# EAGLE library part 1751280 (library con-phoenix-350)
MKDS 1/ 6-3,5 Printklemme Nennstrom: 10 A Bemessungsspannung: 160 V Raster: 3,5 mm Polzahl: 6 Montageart: Löten Anschlussart: Schraubanschluss Anschlussrichtung vom Leiter zur Platine: 0° Source: http://eshop.phoenixcontact.com .. 1751280.pdf
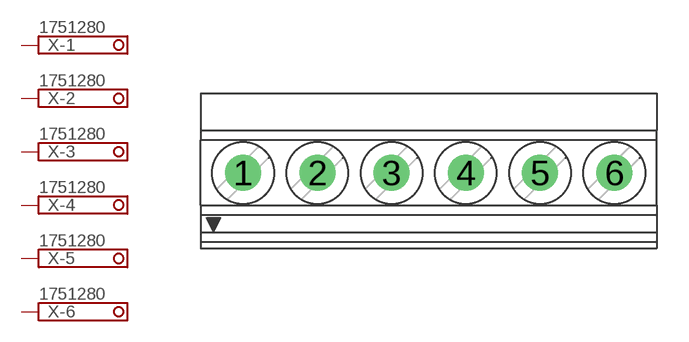
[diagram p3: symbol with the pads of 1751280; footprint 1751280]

Designator prefix X; gates -1=SCHRAUBKLEMME -2=SCHRAUBKLEMME -3=SCHRAUBKLEMME -4=SCHRAUBKLEMME -5=SCHRAUBKLEMME -6=SCHRAUBKLEMME

## 1751280 (MPN: 1751280; OC_FARNELL: unknown; OC_NEWARK: 27R1765)  [1751280]
1  -1:K  pas
2  -2:K  pas
3  -3:K  pas
4  -4:K  pas
5  -5:K  pas
6  -6:K  pas

## Footprint 1751280 (pad centres in mm)
MKDS 1/ 6-3,5 Printklemme Nennstrom: 10 A Bemessungsspannung: 160 V Raster: 3,5 mm Polzahl: 6 Montageart: Löten Anschlussart: Schraubanschluss Anschlussrichtung vom Leiter zur Platine: 0° Source: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
drill 1.1 pad 1.7 round: 1 -8.75,-0.1; 2 -5.25,-0.1; 3 -1.75,-0.1; 4 1.75,-0.1; 5 5.25,-0.1; 6 8.75,-0.1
